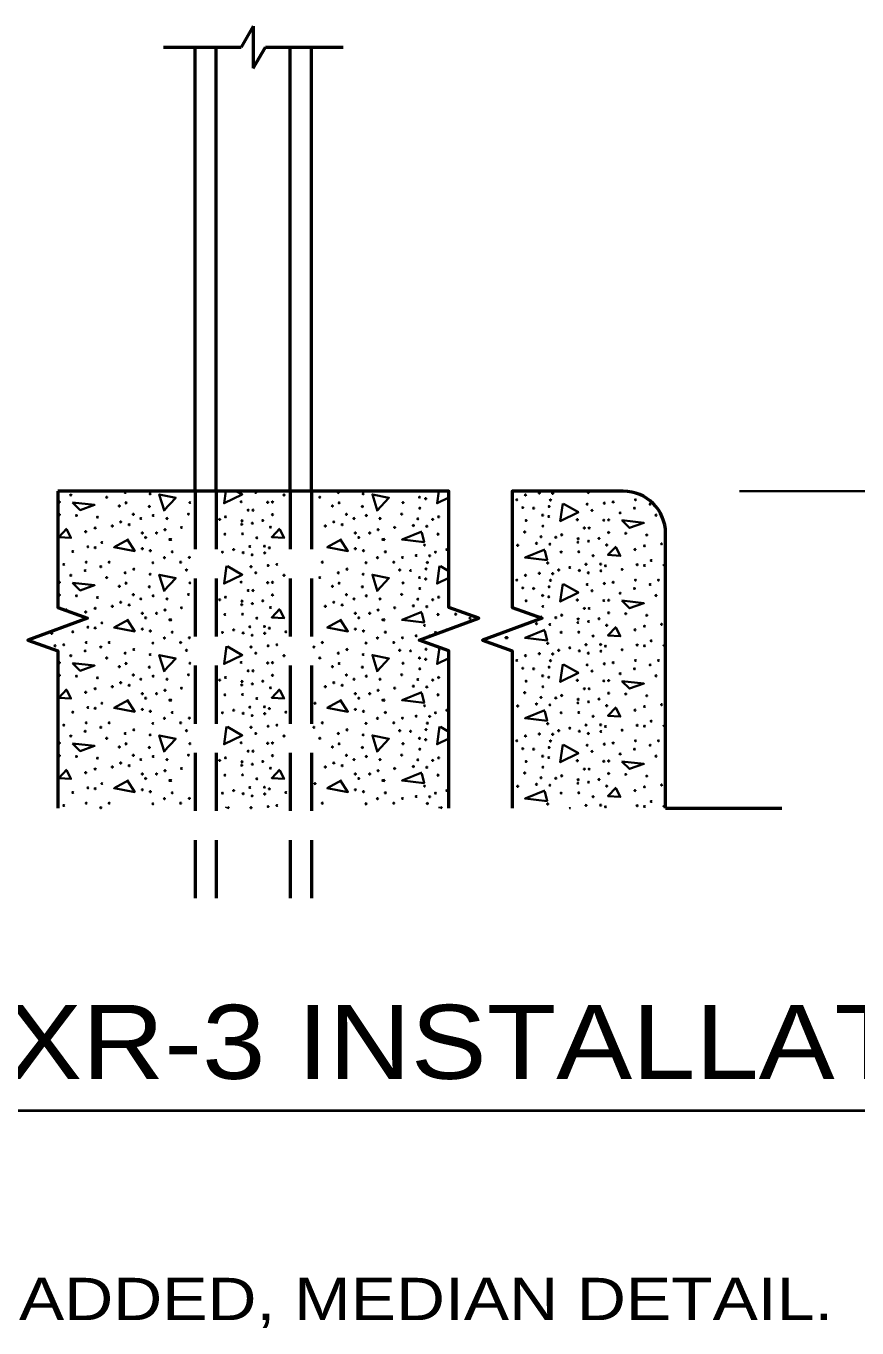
# Model space of a CAD drawing. Extents: x -89 to 766, y -60 to 484.
# Drawn here: x 633.6 to 680.8, y 95.9 to 169.8 of the extents above; entities that cross this region are included whole.
import ezdxf

# ---------------------------------------------------------------- set-up
doc = ezdxf.new("R2010")
doc.units = 0
doc.header["$LTSCALE"] = 1.1
doc.linetypes.add('MEDIUM_DASHED', pattern=[4.5, 3, -1.5])
doc.layers.add('1', color=7, linetype='Continuous', lineweight=35)

msp = doc.modelspace()

# ---------------------------------------------------------------- linework, layer by layer
at = {"layer": '1', "lineweight": 53}
for p, q in [((646.512, 169.817), (645.82, 168.617)), ((646.512, 169.817), (646.512, 167.417)), ((641.412, 168.617), (645.82, 168.617)), ((643.212, 143.417), (643.212, 168.617)), ((644.412, 143.417), (644.412, 168.617)), ((646.512, 167.417), (647.205, 168.617)), ((647.205, 168.617), (651.612, 168.617)), ((648.612, 143.417), (648.612, 168.617)), ((649.812, 143.417), (649.812, 168.617)), ((669.912, 125.417), (669.912, 141.017)), ((669.912, 125.417), (676.512, 125.417))]:
    msp.add_line(p, q, dxfattribs=at)
at = {"layer": '1', "linetype": 'MEDIUM_DASHED', "lineweight": 53}
for p, q in [((643.212, 143.417), (643.212, 119.417)), ((644.412, 143.417), (644.412, 119.417)), ((648.612, 143.417), (648.612, 119.417)), ((649.812, 143.417), (649.812, 119.417))]:
    msp.add_line(p, q, dxfattribs=at)
at = {"layer": '1'}
for p, q in [((674.112, 143.417), (696.912, 143.417)), ((657.137, 139.155), (657.612, 138.883)), ((635.921, 136.731), (635.851, 136.657)), ((635.952, 136.621), (635.921, 136.683)), ((657.463, 134.409), (657.612, 134.323)), ((657.137, 130.035), (657.612, 129.763)), ((644.981, 125.417), (644.993, 125.499)), ((645.041, 125.475), (645.142, 125.417)), ((657.077, 125.417), (657.089, 125.499)), ((657.137, 125.475), (657.238, 125.417))]:
    msp.add_line(p, q, dxfattribs=at)
at = {"layer": '1', "lineweight": 40}
msp.add_line((602.417, 108.258), (698.915, 108.258), dxfattribs=at)
at = {"layer": '1', "lineweight": 53}
for points in [[(635.412, 143.417), (635.412, 136.817), (637.104, 136.201), (633.721, 134.97), (635.412, 134.355), (635.412, 125.417)], [(657.612, 125.417), (657.612, 134.355), (655.921, 134.97), (659.304, 136.201), (657.612, 136.817), (657.612, 143.417), (635.412, 143.417)], [(667.512, 143.417), (661.212, 143.417), (661.212, 136.817), (662.904, 136.201), (659.521, 134.97), (661.212, 134.355), (661.212, 125.417)]]:
    msp.add_lwpolyline(points, dxfattribs=at)
at = {"layer": '1'}
for points in [[(645.562, 143.417), (645.881, 143.235), (644.849, 142.731), (644.947, 143.417)], [(657.612, 143.057), (656.945, 142.731), (657.043, 143.417)], [(641.465, 142.275), (641.177, 143.235), (642.113, 143.043), (641.441, 142.323)], [(653.561, 142.275), (653.273, 143.235), (654.209, 143.043), (653.537, 142.323)], [(664.123, 142.699), (664.963, 142.219), (663.931, 141.715), (664.075, 142.723)], [(635.921, 141.291), (635.465, 140.811), (636.161, 140.763), (635.921, 141.243)], [(648.017, 141.291), (647.561, 140.811), (648.257, 140.763), (648.017, 141.243)], [(639.401, 140.667), (638.609, 140.235), (639.785, 140.019), (639.353, 140.691)], [(651.497, 140.667), (650.705, 140.235), (651.881, 140.019), (651.449, 140.691)], [(656.081, 141.123), (654.953, 140.667), (656.201, 140.523), (656.081, 141.075)], [(663.067, 140.107), (661.939, 139.651), (663.187, 139.507), (663.067, 140.059)], [(667.099, 140.275), (666.643, 139.795), (667.339, 139.747), (667.099, 140.227)], [(645.041, 139.155), (645.881, 138.675), (644.849, 138.171), (644.993, 139.179)], [(657.612, 138.497), (656.945, 138.171), (657.089, 139.179)], [(669.912, 139.287), (669.787, 139.219), (669.912, 139.196)], [(641.465, 137.715), (641.177, 138.675), (642.113, 138.483), (641.441, 137.763)], [(653.561, 137.715), (653.273, 138.675), (654.209, 138.483), (653.537, 137.763)], [(664.123, 138.139), (664.963, 137.659), (663.931, 137.155), (664.075, 138.163)], [(648.017, 136.731), (647.561, 136.251), (648.257, 136.203), (648.017, 136.683)], [(639.401, 136.107), (638.609, 135.675), (639.785, 135.459), (639.353, 136.131)], [(651.497, 136.107), (650.705, 135.675), (651.881, 135.459), (651.449, 136.131)], [(656.081, 136.563), (654.953, 136.107), (656.201, 135.963), (656.081, 136.515)], [(663.067, 135.547), (661.939, 135.091), (663.187, 134.947), (663.067, 135.499)], [(667.099, 135.715), (666.643, 135.235), (667.339, 135.187), (667.099, 135.667)], [(645.041, 134.595), (645.881, 134.115), (644.849, 133.611), (644.993, 134.619)], [(657.612, 133.937), (656.945, 133.611), (657.079, 134.549)], [(669.912, 134.728), (669.787, 134.659), (669.912, 134.636)], [(641.465, 133.155), (641.177, 134.115), (642.113, 133.923), (641.441, 133.203)], [(653.561, 133.155), (653.273, 134.115), (654.209, 133.923), (653.537, 133.203)], [(664.123, 133.579), (664.963, 133.099), (663.931, 132.595), (664.075, 133.603)], [(635.921, 132.171), (635.465, 131.691), (636.161, 131.643), (635.921, 132.123)], [(639.401, 131.547), (638.609, 131.115), (639.785, 130.899), (639.353, 131.571)], [(648.017, 132.171), (647.561, 131.691), (648.257, 131.643), (648.017, 132.123)], [(651.497, 131.547), (650.705, 131.115), (651.881, 130.899), (651.449, 131.571)], [(656.081, 132.003), (654.953, 131.547), (656.201, 131.403), (656.081, 131.955)], [(663.067, 130.987), (661.939, 130.531), (663.187, 130.387), (663.067, 130.939)], [(667.099, 131.155), (666.643, 130.675), (667.339, 130.627), (667.099, 131.107)], [(645.041, 130.035), (645.881, 129.555), (644.849, 129.051), (644.993, 130.059)], [(657.612, 129.377), (656.945, 129.051), (657.089, 130.059)], [(669.912, 130.168), (669.787, 130.099), (669.912, 130.076)], [(641.465, 128.595), (641.177, 129.555), (642.113, 129.363), (641.441, 128.643)], [(653.561, 128.595), (653.273, 129.555), (654.209, 129.363), (653.537, 128.643)], [(664.123, 129.019), (664.963, 128.539), (663.931, 128.035), (664.075, 129.043)], [(635.921, 127.611), (635.465, 127.131), (636.161, 127.083), (635.921, 127.563)], [(648.017, 127.611), (647.561, 127.131), (648.257, 127.083), (648.017, 127.563)], [(656.081, 127.443), (654.953, 126.987), (656.201, 126.843), (656.081, 127.395)], [(639.401, 126.987), (638.609, 126.555), (639.785, 126.339), (639.353, 127.011)], [(651.497, 126.987), (650.705, 126.555), (651.881, 126.339), (651.449, 127.011)], [(663.067, 126.427), (661.939, 125.971), (663.187, 125.827), (663.067, 126.379)], [(667.099, 126.595), (666.643, 126.115), (667.339, 126.067), (667.099, 126.547)], [(669.912, 125.608), (669.787, 125.539), (669.912, 125.516)]]:
    msp.add_lwpolyline(points, dxfattribs=at)
for points in [[(636.257, 142.779), (637.505, 142.635), (636.689, 142.347)], [(667.435, 141.763), (668.683, 141.619), (667.867, 141.331)], [(636.257, 138.219), (637.505, 138.075), (636.689, 137.787)], [(667.435, 137.203), (668.683, 137.059), (667.867, 136.771)], [(636.257, 133.659), (637.505, 133.515), (636.689, 133.227)], [(667.435, 132.643), (668.683, 132.499), (667.867, 132.211)], [(636.257, 129.099), (637.505, 128.955), (636.689, 128.667)], [(667.435, 128.083), (668.683, 127.939), (667.867, 127.651)]]:
    msp.add_lwpolyline(points, close=True, dxfattribs=at)
for centre in [(639.24, 143.343), (646.651, 143.343), (651.336, 143.343), (665.527, 143.345), (635.503, 142.802), (636.155, 143.199), (638.19, 143.072), (639.288, 142.754), (640.655, 143.263), (642.914, 142.77), (645.824, 142.818), (647.327, 142.783), (647.599, 142.802), (648.251, 143.199), (650.286, 143.072), (651.384, 142.754), (652.751, 143.263), (655.01, 142.77), (655.948, 143.072), (656.298, 142.993), (661.471, 142.931), (661.964, 143.202), (662.744, 143.313), (663.38, 142.915), (663.507, 143.297), (665.463, 142.677), (666.433, 142.74), (666.935, 142.804), (668.208, 142.931), (669.035, 142.677), (635.503, 142.086), (636.473, 142.038), (637.666, 141.943), (638.906, 142.579), (639.701, 142.102), (640.131, 141.863), (640.608, 142.547), (640.83, 142.038), (641.61, 141.863), (642.834, 142.118), (644.934, 141.959), (646.222, 142.34), (646.492, 142.34), (647.599, 142.086), (651.002, 142.579), (651.797, 142.102), (652.227, 141.863), (652.704, 142.547), (652.926, 142.038), (653.706, 141.863), (654.93, 142.118), (655.853, 141.847), (655.964, 142.452), (657.03, 141.959), (661.805, 142.486), (662.425, 142.454), (662.934, 142.056), (663.284, 141.977), (663.3, 142.549), (665.733, 142.326), (667.333, 142.183), (668.144, 142.454), (669.369, 142.056), (636.998, 141.121), (637.538, 141.328), (638.508, 141.439), (638.986, 141.672), (639.463, 141.519), (641.498, 141.233), (642.437, 141.36), (644.6, 141.815), (645.856, 141.535), (645.872, 141.736), (646.46, 141.598), (647.049, 141.752), (647.487, 141.376), (650.604, 141.439), (651.082, 141.672), (651.559, 141.519), (653.594, 141.233), (654.533, 141.36), (655.598, 141.471), (656.362, 141.423), (656.696, 141.815), (661.996, 141.754), (662.95, 141.436), (664.906, 141.802), (665.304, 141.324), (665.574, 141.324), (666.41, 141.767), (666.681, 141.786), (637.92, 140.501), (640.21, 141.042), (640.401, 140.787), (641.021, 141.042), (641.769, 140.676), (641.832, 140.676), (644.902, 140.978), (645.904, 140.994), (646.715, 140.771), (652.306, 141.042), (652.497, 140.787), (653.117, 141.042), (653.865, 140.676), (653.928, 140.676), (656.998, 140.978), (661.917, 141.102), (662.585, 140.455), (662.839, 140.831), (663.348, 140.407), (663.682, 140.799), (664.016, 140.942), (664.938, 140.519), (664.954, 140.72), (665.543, 140.582), (666.131, 140.736), (666.681, 141.07), (667.651, 141.022), (668.844, 140.927), (669.687, 140.423), (636.266, 139.992), (637.125, 140.262), (637.538, 140.214), (640.21, 140.151), (640.671, 140.039), (641.467, 139.642), (641.912, 139.976), (642.882, 139.658), (644.759, 139.96), (645.395, 140.103), (645.936, 139.928), (646.317, 140.278), (646.444, 139.801), (647.144, 140.294), (647.16, 139.912), (647.424, 140.199), (652.306, 140.151), (652.767, 140.039), (653.563, 139.642), (654.008, 139.976), (654.978, 139.658), (655.757, 139.769), (656.234, 140.358), (656.521, 139.753), (656.855, 139.96), (657.491, 140.103), (661.519, 140.344), (663.984, 139.962), (664.986, 139.978), (665.797, 139.755), (666.57, 140.36), (668.176, 140.105), (668.717, 140.312), (635.757, 139.26), (636.966, 138.91), (637.029, 139.387), (637.856, 139.133), (638.333, 139.387), (639.733, 138.989), (640.814, 139.355), (642.389, 139.387), (642.723, 138.942), (646.381, 139.133), (647.351, 139.196), (647.853, 139.26), (650.429, 139.387), (651.829, 138.989), (652.91, 139.355), (654.485, 139.387), (654.819, 138.942), (655.439, 138.91), (656.314, 139.005), (656.393, 139.371), (663.221, 139.341), (663.841, 138.944), (664.477, 139.087), (665.018, 138.912), (665.399, 139.262), (666.227, 139.278), (666.242, 138.896), (666.506, 139.182), (667.444, 138.976), (668.303, 139.246), (668.717, 139.198), (669.098, 139.485), (635.503, 138.242), (636.155, 138.639), (638.19, 138.512), (639.24, 138.783), (639.288, 138.194), (640.655, 138.703), (642.914, 138.21), (645.824, 138.258), (646.651, 138.783), (647.327, 138.223), (647.599, 138.242), (648.251, 138.639), (650.286, 138.512), (651.336, 138.783), (651.384, 138.194), (652.751, 138.703), (655.01, 138.21), (655.948, 138.512), (656.298, 138.433), (661.471, 138.371), (661.964, 138.642), (662.744, 138.753), (663.38, 138.355), (663.507, 138.737), (665.527, 138.785), (666.433, 138.18), (666.935, 138.244), (668.208, 138.371), (669.512, 138.371), (635.503, 137.526), (636.473, 137.478), (638.906, 138.019), (639.701, 137.542), (640.608, 137.987), (640.83, 137.478), (642.834, 137.558), (646.222, 137.78), (646.492, 137.78), (647.599, 137.526), (651.002, 138.019), (651.797, 137.542), (652.704, 137.987), (652.926, 137.478), (654.93, 137.558), (655.964, 137.892), (661.805, 137.926), (662.425, 137.894), (662.934, 137.496), (663.284, 137.417), (663.3, 137.989), (665.463, 138.117), (665.733, 137.766), (667.333, 137.623), (668.144, 137.894), (669.035, 138.117), (669.369, 137.496), (637.538, 136.768), (637.666, 137.383), (638.508, 136.879), (638.986, 137.112), (639.463, 136.959), (640.131, 137.303), (641.498, 136.673), (641.61, 137.303), (642.437, 136.8), (644.6, 137.255), (644.934, 137.399), (645.856, 136.975), (645.872, 137.176), (646.46, 137.038), (647.049, 137.192), (647.487, 136.816), (650.604, 136.879), (651.082, 137.112), (651.559, 136.959), (652.227, 137.303), (653.594, 136.673), (653.706, 137.303), (654.533, 136.8), (655.598, 136.911), (655.853, 137.287), (656.362, 136.863), (656.696, 137.255), (657.03, 137.399), (661.996, 137.194), (662.95, 136.876), (664.906, 137.242), (665.304, 136.764), (665.574, 136.764), (666.41, 137.207), (666.681, 137.226), (636.998, 136.561), (637.92, 135.941), (640.21, 136.482), (640.401, 136.227), (641.021, 136.482), (641.769, 136.116), (641.832, 136.116), (644.902, 136.418), (645.904, 136.434), (646.715, 136.211), (652.306, 136.482), (652.497, 136.227), (653.117, 136.482), (653.865, 136.116), (653.928, 136.116), (656.998, 136.418), (658, 136.434), (658.811, 136.211), (662.839, 136.271), (663.682, 136.239), (664.016, 136.382), (664.938, 135.959), (664.954, 136.16), (665.543, 136.022), (666.131, 136.176), (666.681, 136.51), (667.651, 136.462), (668.844, 136.367), (635.064, 135.352), (636.266, 135.432), (637.125, 135.702), (637.538, 135.654), (640.21, 135.591), (640.671, 135.479), (641.912, 135.416), (644.759, 135.4), (645.395, 135.543), (645.936, 135.368), (646.317, 135.718), (646.444, 135.241), (647.144, 135.734), (647.16, 135.352), (647.424, 135.639), (648.362, 135.432), (652.306, 135.591), (652.767, 135.479), (654.008, 135.416), (655.757, 135.209), (656.234, 135.798), (656.855, 135.4), (662.585, 135.895), (663.348, 135.847), (663.984, 135.402), (664.986, 135.418), (665.797, 135.195), (666.57, 135.8), (668.176, 135.545), (668.717, 135.752), (669.687, 135.863), (635.255, 134.636), (635.757, 134.7), (637.029, 134.827), (637.856, 134.573), (638.333, 134.827), (640.814, 134.795), (641.467, 135.082), (642.389, 134.827), (642.882, 135.098), (646.381, 134.573), (647.351, 134.636), (647.853, 134.7), (649.952, 134.573), (650.429, 134.827), (652.91, 134.795), (653.563, 135.082), (654.485, 134.827), (654.978, 135.098), (660.851, 135.1), (660.915, 135.1), (663.221, 134.781), (664.477, 134.527), (665.399, 134.702), (666.227, 134.718), (666.506, 134.622), (668.303, 134.686), (668.717, 134.638), (669.098, 134.925), (636.155, 134.079), (636.966, 134.35), (638.19, 133.952), (639.24, 134.223), (639.733, 134.429), (640.655, 134.143), (642.723, 134.382), (646.651, 134.223), (648.251, 134.079), (650.286, 133.952), (651.336, 134.223), (651.829, 134.429), (652.751, 134.143), (654.819, 134.382), (655.439, 134.35), (655.948, 133.952), (656.298, 133.873), (656.314, 134.445), (661.471, 133.811), (661.964, 134.082), (662.744, 134.193), (663.38, 133.795), (663.507, 134.177), (663.841, 134.384), (665.018, 134.352), (665.527, 134.225), (666.242, 134.336), (667.444, 134.416), (668.208, 133.811), (669.512, 133.811), (635.503, 133.682), (638.906, 133.459), (639.288, 133.634), (639.701, 132.982), (640.608, 133.427), (642.834, 132.998), (642.914, 133.65), (645.824, 133.698), (646.222, 133.22), (646.492, 133.22), (647.327, 133.663), (647.599, 133.682), (651.002, 133.459), (651.384, 133.634), (651.797, 132.982), (652.704, 133.427), (654.93, 132.998), (655.01, 133.65), (655.964, 133.332), (661.805, 133.366), (662.425, 133.334), (663.3, 133.429), (665.463, 133.557), (665.733, 133.206), (666.433, 133.62), (666.935, 133.684), (667.333, 133.063), (668.144, 133.334), (669.035, 133.557), (635.503, 132.966), (636.473, 132.918), (637.666, 132.823), (638.508, 132.319), (638.986, 132.552), (639.463, 132.399), (640.131, 132.743), (640.83, 132.918), (641.61, 132.743), (642.437, 132.24), (644.6, 132.695), (644.934, 132.839), (645.856, 132.415), (645.872, 132.616), (646.46, 132.478), (647.049, 132.632), (647.487, 132.256), (647.599, 132.966), (650.604, 132.319), (651.082, 132.552), (651.559, 132.399), (652.227, 132.743), (652.926, 132.918), (653.706, 132.743), (654.533, 132.24), (655.598, 132.351), (655.853, 132.727), (656.362, 132.303), (656.696, 132.695), (657.03, 132.839), (661.996, 132.634), (662.934, 132.936), (662.95, 132.316), (663.284, 132.857), (664.906, 132.682), (666.41, 132.647), (666.681, 132.666), (669.369, 132.936), (636.998, 132.001), (637.538, 132.208), (640.21, 131.922), (640.401, 131.667), (641.021, 131.922), (641.498, 132.113), (641.769, 131.556), (641.832, 131.556), (644.902, 131.858), (645.904, 131.874), (646.715, 131.651), (652.306, 131.922), (652.497, 131.667), (653.117, 131.922), (653.594, 132.113), (653.865, 131.556), (653.928, 131.556), (656.998, 131.858), (661.917, 131.982), (662.839, 131.711), (663.682, 131.679), (664.016, 131.822), (664.954, 131.6), (665.304, 132.204), (665.574, 132.204), (666.131, 131.616), (666.681, 131.95), (667.651, 131.902), (668.844, 131.807), (636.266, 130.872), (637.125, 131.142), (637.538, 131.094), (637.92, 131.381), (640.21, 131.031), (640.671, 130.919), (641.912, 130.856), (644.759, 130.84), (645.395, 130.983), (645.936, 130.808), (646.317, 131.158), (647.144, 131.174), (647.16, 130.792), (647.424, 131.079), (648.362, 130.872), (650.016, 131.381), (652.306, 131.031), (652.767, 130.919), (654.008, 130.856), (656.234, 131.238), (656.855, 130.84), (657.491, 130.983), (661.519, 131.224), (662.585, 131.335), (663.348, 131.287), (663.984, 130.842), (664.938, 131.399), (664.986, 130.858), (665.543, 131.462), (666.57, 131.24), (668.176, 130.985), (668.717, 131.192), (669.687, 131.303), (635.757, 130.14), (637.029, 130.267), (638.333, 130.267), (640.814, 130.235), (641.467, 130.522), (642.389, 130.267), (642.882, 130.538), (646.444, 130.681), (647.351, 130.076), (647.853, 130.14), (650.429, 130.267), (652.91, 130.235), (653.563, 130.522), (654.485, 130.267), (654.978, 130.538), (655.757, 130.649), (656.393, 130.251), (656.521, 130.633), (663.221, 130.221), (665.399, 130.142), (665.797, 130.635), (666.227, 130.158), (666.506, 130.062), (668.303, 130.126), (668.717, 130.078), (669.098, 130.365), (636.155, 129.519), (636.966, 129.79), (637.856, 130.013), (638.19, 129.392), (639.24, 129.663), (639.733, 129.869), (640.655, 129.583), (642.723, 129.822), (646.381, 130.013), (646.651, 129.663), (648.251, 129.519), (649.952, 130.013), (650.286, 129.392), (651.336, 129.663), (651.829, 129.869), (652.751, 129.583), (654.819, 129.822), (655.439, 129.79), (655.948, 129.392), (656.298, 129.313), (656.314, 129.885), (661.964, 129.522), (662.744, 129.633), (663.507, 129.617), (663.841, 129.824), (664.477, 129.967), (665.018, 129.792), (665.527, 129.665), (666.242, 129.776), (667.444, 129.856), (635.503, 129.122), (638.906, 128.899), (639.288, 129.074), (640.608, 128.867), (642.914, 129.09), (645.824, 129.138), (646.222, 128.66), (646.492, 128.66), (647.327, 129.103), (647.599, 129.122), (651.002, 128.899), (651.384, 129.074), (652.704, 128.867), (655.01, 129.09), (655.964, 128.772), (661.471, 129.251), (661.805, 128.806), (662.425, 128.774), (663.3, 128.869), (663.38, 129.235), (665.463, 128.997), (665.733, 128.646), (666.433, 129.06), (666.935, 129.124), (668.144, 128.774), (668.208, 129.251), (669.035, 128.997), (669.512, 129.251), (635.503, 128.406), (636.473, 128.358), (637.666, 128.263), (638.986, 127.992), (639.463, 127.839), (639.701, 128.422), (640.131, 128.183), (640.83, 128.358), (641.61, 128.183), (642.834, 128.438), (644.6, 128.135), (644.934, 128.279), (645.856, 127.855), (645.872, 128.056), (646.46, 127.918), (647.049, 128.072), (647.599, 128.406), (651.082, 127.992), (651.559, 127.839), (651.797, 128.422), (652.227, 128.183), (652.926, 128.358), (653.706, 128.183), (654.93, 128.438), (655.853, 128.167), (656.696, 128.135), (657.03, 128.279), (661.996, 128.074), (662.934, 128.376), (663.284, 128.297), (664.906, 128.122), (666.41, 128.087), (666.681, 128.106), (667.333, 128.503), (669.369, 128.376), (636.998, 127.441), (637.538, 127.648), (638.508, 127.759), (640.21, 127.362), (640.401, 127.107), (641.021, 127.362), (641.498, 127.553), (642.437, 127.68), (644.902, 127.298), (645.904, 127.314), (646.715, 127.091), (647.487, 127.696), (650.604, 127.759), (652.306, 127.362), (652.497, 127.107), (653.117, 127.362), (653.594, 127.553), (654.533, 127.68), (655.598, 127.791), (656.362, 127.743), (656.998, 127.298), (661.917, 127.422), (662.839, 127.151), (662.95, 127.756), (663.682, 127.119), (664.016, 127.262), (665.304, 127.644), (665.574, 127.644), (666.681, 127.39), (667.651, 127.342), (668.844, 127.247), (637.125, 126.582), (637.538, 126.534), (637.92, 126.821), (640.21, 126.471), (640.671, 126.359), (641.769, 126.996), (641.832, 126.996), (645.395, 126.423), (646.317, 126.598), (647.144, 126.614), (647.424, 126.519), (650.016, 126.821), (652.306, 126.471), (652.767, 126.359), (653.865, 126.996), (653.928, 126.996), (656.234, 126.678), (657.491, 126.423), (661.519, 126.664), (662.585, 126.775), (663.348, 126.727), (664.938, 126.839), (664.954, 127.04), (665.543, 126.902), (666.131, 127.056), (666.57, 126.68), (668.176, 126.425), (668.717, 126.632), (669.687, 126.743), (636.266, 126.312), (637.029, 125.707), (638.333, 125.707), (640.814, 125.675), (641.467, 125.962), (641.912, 126.296), (642.389, 125.707), (642.882, 125.978), (644.759, 126.28), (645.936, 126.248), (646.444, 126.121), (647.16, 126.232), (648.362, 126.312), (650.429, 125.707), (652.91, 125.675), (653.563, 125.962), (654.008, 126.296), (654.485, 125.707), (654.978, 125.978), (655.757, 126.089), (656.393, 125.691), (656.521, 126.073), (656.855, 126.28), (663.221, 125.661), (663.984, 126.282), (664.986, 126.298), (665.797, 126.075), (666.227, 125.598), (669.098, 125.805), (635.757, 125.58), (637.856, 125.453), (646.381, 125.453), (647.351, 125.516), (647.853, 125.58), (665.399, 125.582), (666.506, 125.502), (668.303, 125.566), (668.717, 125.518)]:
    msp.add_circle(centre, 0.0318, dxfattribs=at)
at = {"layer": '1', "lineweight": 53}
msp.add_arc((667.512, 141.017), 2.4, 0, 90, dxfattribs=at)
at = {"layer": '1'}
for centre, start, end in [((635.391, 141.376), 311.33779, 48.66221), ((635.391, 136.816), 355.21358, 48.66221), ((661.917, 136.542), 14.42148, 125.57967), ((656.521, 135.193), 12.06213, 207.93862), ((657.491, 135.543), 17.37164, 202.62912), ((656.393, 134.811), 182.92017, 317.08316), ((635.391, 132.256), 311.33779, 48.66221), ((635.391, 127.696), 311.33779, 48.66221), ((664.477, 125.407), 18.42284, 161.57716)]:
    msp.add_arc(centre, 0.0318, start, end, dxfattribs=at)

# ---------------------------------------------------------------- texts
for s, height, width, p in [('TYPICAL XR-3 INSTALLATION', 4.2, 1.15, (603.769, 110.062)), ('XR-9 FROM .064 TO .125, SPACING FORMULA ADDED, MEDIAN DETAIL.', 2.4, 1.2, (548.036, 96.37))]:
    msp.add_text(s, height=height, dxfattribs=dict(at, width=width)).set_placement(p)

doc.saveas('drawing.dxf')
